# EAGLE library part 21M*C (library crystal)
Monolithic Crystal Filters Source: www.vanlong.com
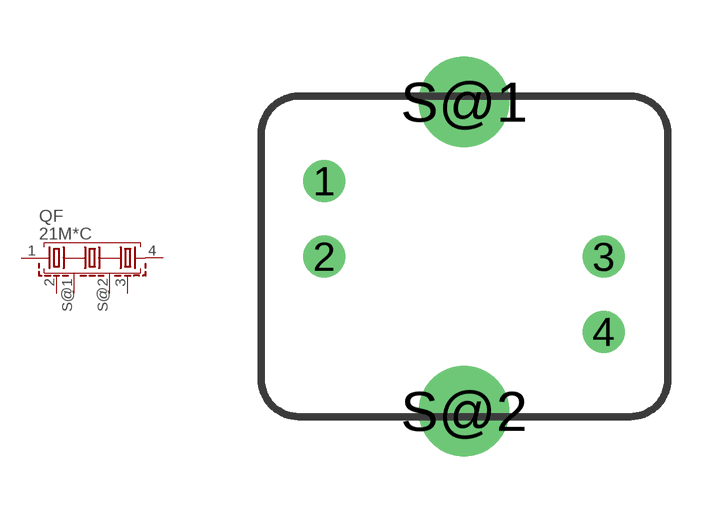
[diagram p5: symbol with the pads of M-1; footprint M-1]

Designator prefix QF

## 21M15C (OC_FARNELL: unknown; OC_NEWARK: unknown), 21M20C (OC_FARNELL: unknown; OC_NEWARK: unknown)  [M-1]
1  1  pas
2  2  pas
3  3  pas
4  4  pas
S@1  S  pas
S@2  S  pas

## Footprint M-1 (pad centres in mm)
Monolithic Crystal Filters Source: www.vanlong.com
drill 0.6 pad 1.016 round: 1 -3.7,2; 2 -3.7,0; 3 3.7,0; 4 3.7,-2
drill 1.6 pad 1.93 round: S@1 0,4.1; S@2 0,-4.1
